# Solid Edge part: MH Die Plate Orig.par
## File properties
Author: Dan
Template: Metric Part.par
Last saved by: Dan
Revision: 2
Application: Solid Edge
Accuracy: 0.990
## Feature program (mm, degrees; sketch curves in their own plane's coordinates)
sketch for "unnamed Protrusion 1" plane through (0, 0, 0) normal (0, 0, 1) x-axis (1, 0, 0)
extrude "unnamed Protrusion 1" add finite 46 along -normal
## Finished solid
Body 1: solid body, 6 faces, 12 edges, 8 vertices.
  Faces by surface: plane 6
  Edges by curve: line 12
Bounding box of the edges (mm): 396.000 x 396.000 x 46.000, from (-198, -198, -46) to (198, 198, 0).
Planar faces by outward normal: +x 1, +y 1, +z 1, -x 1, -y 1, -z 1
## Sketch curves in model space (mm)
circle centre (-75, -75, 0) radius 62.5
circle centre (75, -75, 0) radius 62.5
circle centre (75, 75, 0) radius 62.5
circle centre (-75, 75, 0) radius 62.5
line (140, 198, 0) -> (140, -198, 0)
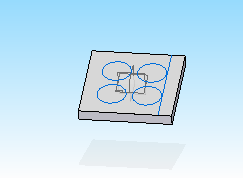
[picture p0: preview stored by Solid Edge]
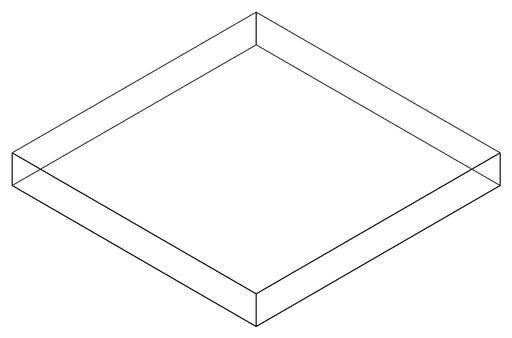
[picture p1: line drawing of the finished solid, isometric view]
